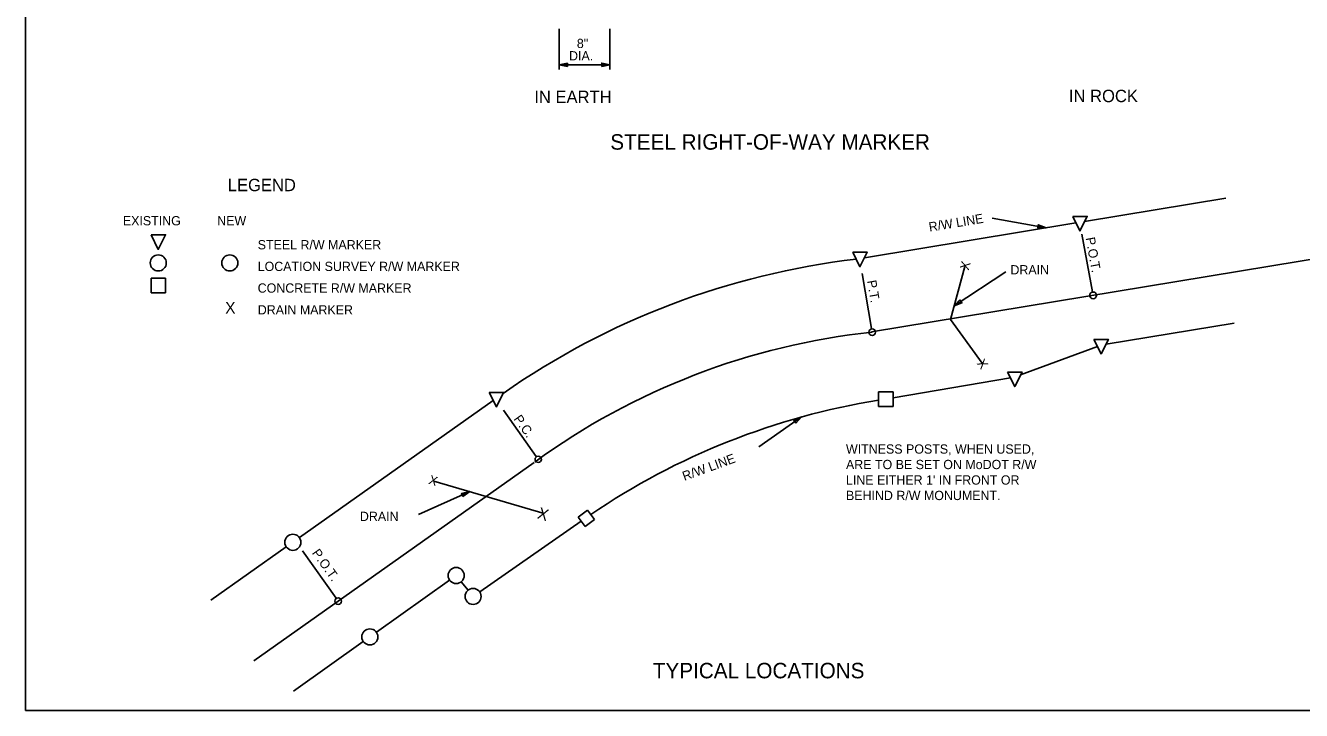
# Model space of a CAD drawing. Extents: x -439.1 to -392.2, y -458.1 to -436.2.
# Drawn here: x -439.11 to -418.5, y -458.05 to -446.98 of the extents above; entities that cross this region are included whole.
import ezdxf

# ---------------------------------------------------------------- set-up
doc = ezdxf.new("R2010")
doc.units = 0
for name, color, linetype in [('Bridge-Named Boundary', 7, 'Continuous'), ('Level 4', 7, 'Continuous'), ('Level 45', 7, 'Continuous')]:
    doc.layers.add(name, color=color, linetype=linetype)

msp = doc.modelspace()

# ---------------------------------------------------------------- linework, layer by layer
at = {"layer": 'Bridge-Named Boundary'}
msp.add_lwpolyline([(-439.109, -458.051), (-407.859, -458.051), (-407.859, -437.676), (-439.109, -437.676)], close=True, dxfattribs=at)
at = {"layer": 'Level 4'}
for p, q in [((-430.489, -447.035), (-430.489, -447.692)), ((-429.67, -447.035), (-429.67, -447.692)), ((-430.489, -447.617), (-429.67, -447.617)), ((-422.002, -450.15), (-419.722, -449.772)), ((-422.626, -450.253), (-423.495, -450.095)), ((-425.559, -450.738), (-422.143, -450.173)), ((-421.875, -451.288), (-422.045, -450.352)), ((-425.445, -451.935), (-417.985, -450.702)), ((-424.171, -451.732), (-423.935, -450.875)), ((-437.082, -451.3), (-437.082, -451.065)), ((-437.082, -451.065), (-436.848, -451.065)), ((-436.848, -451.065), (-436.848, -451.3)), ((-425.443, -451.881), (-425.598, -450.992)), ((-424.111, -451.514), (-423.276, -450.964)), ((-436.848, -451.3), (-437.082, -451.3)), ((-424.171, -451.732), (-423.66, -452.44)), ((-421.657, -452.132), (-419.589, -451.79)), ((-423.036, -452.628), (-421.797, -452.168)), ((-423.201, -452.676), (-425.096, -452.999)), ((-425.33, -453.138), (-425.33, -452.903)), ((-425.33, -452.903), (-425.096, -452.903)), ((-425.096, -452.903), (-425.096, -453.138)), ((-434.685, -455.257), (-431.556, -453.042)), ((-425.096, -453.138), (-425.33, -453.138)), ((-430.859, -453.947), (-431.388, -453.2)), ((-426.576, -453.308), (-427.265, -453.79)), ((-435.42, -457.248), (-430.895, -454.044)), ((-432.515, -454.344), (-430.734, -454.866)), ((-431.933, -454.515), (-432.763, -454.885)), ((-430.183, -454.926), (-430.031, -454.815)), ((-430.031, -454.815), (-429.921, -454.967)), ((-430.135, -454.991), (-431.773, -456.133)), ((-430.072, -455.077), (-430.183, -454.926)), ((-429.921, -454.967), (-430.072, -455.077)), ((-436.114, -456.269), (-434.897, -455.408)), ((-434.089, -456.238), (-434.634, -455.469)), ((-432.259, -455.945), (-433.441, -456.787)), ((-432.071, -455.971), (-431.962, -456.107)), ((-433.654, -456.938), (-434.778, -457.738))]:
    msp.add_line(p, q, dxfattribs=at)
for points in [[(-430.356, -447.589), (-430.489, -447.617), (-430.356, -447.644)], [(-429.803, -447.644), (-429.67, -447.617), (-429.803, -447.589)], [(-422.195, -450.068), (-422.078, -450.302), (-421.961, -450.068)], [(-422.761, -450.256), (-422.626, -450.253), (-422.751, -450.202)], [(-422.761, -450.256), (-422.626, -450.253), (-422.751, -450.202)], [(-437.082, -450.365), (-436.965, -450.6), (-436.848, -450.365)], [(-425.748, -450.647), (-425.631, -450.881), (-425.514, -450.647)], [(-424.016, -451.418), (-424.111, -451.514), (-423.985, -451.464)], [(-424.016, -451.418), (-424.111, -451.514), (-423.985, -451.464)], [(-421.853, -452.056), (-421.736, -452.29), (-421.619, -452.056)], [(-423.248, -452.583), (-423.131, -452.817), (-423.014, -452.583)], [(-431.621, -452.912), (-431.504, -453.146), (-431.387, -452.912)], [(-426.669, -453.407), (-426.576, -453.308), (-426.7, -453.361)], [(-426.669, -453.407), (-426.576, -453.308), (-426.7, -453.361)], [(-432.043, -454.594), (-431.933, -454.515), (-432.066, -454.544)], [(-432.043, -454.594), (-431.933, -454.515), (-432.066, -454.544)]]:
    msp.add_lwpolyline(points, close=True, dxfattribs=at)
for centre, radius in [((-436.965, -450.819), 0.13), ((-435.809, -450.819), 0.13), ((-421.866, -451.343), 0.054), ((-425.433, -451.938), 0.054), ((-430.828, -453.993), 0.0506), ((-434.791, -455.333), 0.13), ((-432.153, -455.87), 0.13), ((-431.88, -456.208), 0.13), ((-434.058, -456.283), 0.054), ((-433.547, -456.862), 0.13)]:
    msp.add_circle(centre, radius, dxfattribs=at)
for centre, radius, start, end in [((-424.241, -463.153), 12.48, 96.6816, 124.9744), ((-424.241, -463.153), 11.28, 96.0612, 126.0736), ((-423.51, -464.401), 11.508, 99.1011, 124.2145)]:
    msp.add_arc(centre, radius, start, end, dxfattribs=at)

# ---------------------------------------------------------------- texts
for s, height, p in [('IN EARTH', 0.2, (-430.891, -448.236)), ('IN ROCK', 0.2, (-422.256, -448.221)), ('STEEL RIGHT-OF-WAY MARKER', 0.25, (-429.664, -448.989)), ('LEGEND', 0.2, (-435.842, -449.66)), ('EXISTING', 0.15, (-437.537, -450.212)), ('NEW', 0.15, (-436.013, -450.212)), ('STEEL R/W MARKER', 0.15, (-435.359, -450.6)), ('LOCATION SURVEY R/W MARKER', 0.15, (-435.359, -450.95)), ('DRAIN', 0.15, (-423.201, -451.005)), ('CONCRETE R/W MARKER', 0.15, (-435.359, -451.3)), ('X', 0.187, (-435.884, -451.638)), ('DRAIN MARKER', 0.15, (-435.358, -451.652)), ('DRAIN', 0.15, (-433.708, -454.989)), ('TYPICAL LOCATIONS', 0.25, (-428.977, -457.531))]:
    msp.add_text(s, height=height, dxfattribs=at).set_placement(p)
for s, height, rotation, p in [('R/W LINE', 0.15, 9.4, (-424.507, -450.315)), ('P.O.T.', 0.15, 280.3, (-421.987, -450.416)), ('X', 0.15, 74.6, (-423.877, -450.946)), ('P.T.', 0.15, 280, (-425.518, -451.11)), ('X', 0.15, 306, (-423.751, -452.442)), ('P.C.', 0.15, 305.3, (-431.231, -453.34)), ('R/W LINE', 0.15, 20, (-428.467, -454.342)), ('X', 0.15, 342.7, (-432.61, -454.386)), ('X', 0.187, 342.7, (-430.855, -454.942)), ('P.O.T.', 0.15, 305.3, (-434.489, -455.506))]:
    msp.add_text(s, height=height, rotation=rotation, dxfattribs=at).set_placement(p)
at = {"layer": 'Level 45'}
for s, p in [('8"', (-430.204, -447.347)), ('DIA.', (-430.33, -447.547)), ('WITNESS POSTS, WHEN USED,', (-425.857, -453.901)), ('ARE TO BE SET ON MoDOT R/W ', (-425.857, -454.151)), ("LINE EITHER 1' IN FRONT OR", (-425.857, -454.401)), ('BEHIND R/W MONUMENT.', (-425.857, -454.651))]:
    msp.add_text(s, height=0.15, dxfattribs=at).set_placement(p)

doc.saveas('drawing.dxf')
